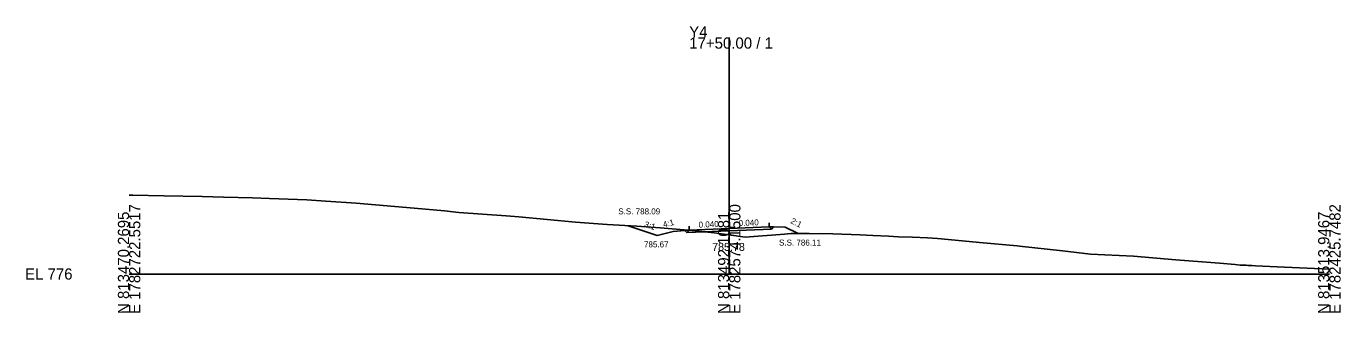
# Model space of a CAD drawing. Extents: x -26 to 3903, y -10 to 9562.
# Drawn here: x -25.7 to 302.8, y 9490.3 to 9562 of the extents above; entities that cross this region are included whole.
import ezdxf

# ---------------------------------------------------------------- set-up
doc = ezdxf.new("R2010")
doc.units = 0
for name, color, linetype in [('Exist Cross Section Cell', 7, 'Continuous'), ('Exist XS Center Line Elevation Label', 7, 'Continuous'), ('Exist XS Ground Line', 7, 'Continuous'), ('Prop XS Ditch Slope Text', 7, 'Continuous'), ('Prop XS Ditch Standard Text', 7, 'Continuous'), ('Prop XS Dump Level', 7, 'Continuous'), ('Prop XS Earthwork Shape', 7, 'Continuous'), ('Prop XS EOT Tick Mark', 7, 'Continuous'), ('Prop XS Finish Grade', 7, 'Continuous'), ('Prop XS Finish Grade Earthwork', 7, 'Continuous'), ('Prop XS Finish Grade Pavement', 7, 'Continuous'), ('Prop XS Pvmt Edge Slope', 7, 'Continuous'), ('Prop XS SE Text', 7, 'Continuous'), ('Prop XS Side Slope Text', 7, 'Continuous'), ('Prop XS SS Elevation Text', 7, 'Continuous'), ('Prop XS Subgrade Earthwork', 7, 'Continuous')]:
    doc.layers.add(name, color=color, linetype=linetype)

msp = doc.modelspace()

# ---------------------------------------------------------------- linework, layer by layer
at = {"layer": 'Exist Cross Section Cell'}
for p, q in [((150, 9500), (150, 9559.19)), ((0, 9500), (150, 9500)), ((150, 9500), (300, 9500))]:
    msp.add_line(p, q, dxfattribs=at)
at = {"layer": 'Exist XS Ground Line'}
for p, q in [((0, 9519.73), (0.95, 9519.72)), ((0.95, 9519.72), (8.66, 9519.54)), ((8.66, 9519.54), (18.3, 9519.42)), ((18.3, 9519.42), (23.59, 9519.22)), ((23.59, 9519.22), (30.83, 9519.04)), ((30.83, 9519.04), (35.09, 9518.88)), ((35.09, 9518.88), (44.46, 9518.54)), ((44.46, 9518.54), (49.19, 9518.2)), ((49.19, 9518.2), (56.76, 9517.76)), ((56.76, 9517.76), (71.27, 9516.51)), ((71.27, 9516.51), (78.85, 9515.81)), ((78.85, 9515.81), (82.41, 9515.41)), ((82.41, 9515.41), (94.26, 9514.55)), ((94.26, 9514.55), (95.37, 9514.47)), ((95.37, 9514.47), (97.41, 9514.31)), ((97.41, 9514.31), (111.58, 9513.01)), ((111.58, 9513.01), (119.53, 9512.39)), ((119.53, 9512.39), (126.88, 9511.97)), ((126.88, 9511.97), (132.73, 9511.53)), ((132.73, 9511.53), (134.72, 9511.38)), ((134.72, 9511.38), (141.73, 9510.78)), ((141.73, 9510.78), (143.87, 9510.55)), ((143.87, 9510.55), (146.24, 9510.3)), ((146.24, 9510.3), (150, 9509.78)), ((150, 9509.78), (153.95, 9509.22)), ((153.95, 9509.22), (163.79, 9509.99)), ((163.79, 9509.99), (165.52, 9510.11)), ((165.52, 9510.11), (169.95, 9510.1)), ((169.95, 9510.1), (175.94, 9510.03)), ((175.94, 9510.03), (182.72, 9509.78)), ((182.72, 9509.78), (185.89, 9509.65)), ((185.89, 9509.65), (189.83, 9509.48)), ((189.83, 9509.48), (192.29, 9509.33)), ((192.29, 9509.33), (195.78, 9509.18)), ((195.78, 9509.18), (199.57, 9509.09)), ((199.57, 9509.09), (202.04, 9508.88)), ((202.04, 9508.88), (208.19, 9508.31)), ((208.19, 9508.31), (212.54, 9507.88)), ((212.54, 9507.88), (221.98, 9507.04)), ((221.98, 9507.04), (222.53, 9506.98)), ((222.53, 9506.98), (233.29, 9505.77)), ((233.29, 9505.77), (240.29, 9504.98)), ((240.29, 9504.98), (251.04, 9504.5)), ((251.04, 9504.5), (261.65, 9503.58)), ((261.65, 9503.58), (272.55, 9502.68)), ((272.55, 9502.68), (276.46, 9502.34)), ((276.46, 9502.34), (277.69, 9502.23)), ((277.69, 9502.23), (279.2, 9502.17)), ((279.2, 9502.17), (279.64, 9502.15)), ((279.64, 9502.15), (280.63, 9502.11)), ((280.63, 9502.11), (281.51, 9502.08)), ((281.51, 9502.08), (286.99, 9501.78)), ((286.99, 9501.78), (300, 9501.25))]:
    msp.add_line(p, q, dxfattribs=at)
at = {"layer": 'Prop XS Dump Level'}
for p, q in [((140, 9510.99), (150, 9511.39)), ((150, 9511.39), (160, 9511.79))]:
    msp.add_line(p, q, dxfattribs=at)
at = {"layer": 'Prop XS Earthwork Shape'}
for points in [[(136, 9510.67), (132, 9509.67), (124.73, 9512.09), (126.88, 9511.97), (132.73, 9511.53), (134.72, 9511.38), (141.73, 9510.78), (143.79, 9510.56), (139.39, 9510.38), (138.87, 9510.9)], [(143.87, 9510.55), (146.24, 9510.3), (150, 9509.78), (153.95, 9509.22), (163.79, 9509.99), (165.52, 9510.11), (167.2, 9510.11), (164, 9511.71), (161.1, 9511.77), (160.56, 9511.23), (150.02, 9510.81), (143.79, 9510.56)]]:
    msp.add_lwpolyline(points, close=True, dxfattribs=at)
at = {"layer": 'Prop XS EOT Tick Mark'}
for p, q in [((140, 9510.99), (140, 9511.99)), ((160, 9511.79), (160, 9512.79))]:
    msp.add_line(p, q, dxfattribs=at)
at = {"layer": 'Prop XS Finish Grade'}
for p, q in [((160, 9511.79), (161.1, 9511.77)), ((140, 9510.99), (138.87, 9510.9))]:
    msp.add_line(p, q, dxfattribs=at)
at = {"layer": 'Prop XS Finish Grade Earthwork'}
for p, q in [((132, 9509.67), (124.73, 9512.09)), ((161.1, 9511.77), (164, 9511.71)), ((164, 9511.71), (167.2, 9510.11)), ((136, 9510.67), (132, 9509.67)), ((138.87, 9510.9), (136, 9510.67))]:
    msp.add_line(p, q, dxfattribs=at)
at = {"layer": 'Prop XS Finish Grade Pavement'}
for p, q in [((140, 9510.99), (150, 9511.39)), ((150, 9511.39), (160, 9511.79))]:
    msp.add_line(p, q, dxfattribs=at)
at = {"layer": 'Prop XS Pvmt Edge Slope'}
for p, q in [((160, 9511.79), (160.56, 9511.23)), ((140, 9510.99), (139.39, 9510.38))]:
    msp.add_line(p, q, dxfattribs=at)
at = {"layer": 'Prop XS Subgrade Earthwork'}
for p, q in [((150.02, 9510.81), (160.56, 9511.23)), ((160.56, 9511.23), (161.1, 9511.77)), ((139.39, 9510.38), (138.87, 9510.9)), ((139.39, 9510.38), (150.02, 9510.81))]:
    msp.add_line(p, q, dxfattribs=at)

# ---------------------------------------------------------------- texts
at = {"layer": 'Exist Cross Section Cell'}
for s, p in [('Y4', (140, 9559.19)), ('17+50.00 / 1', (140, 9556.39)), ('EL 776', (-26, 9498.6))]:
    msp.add_text(s, height=2.8, dxfattribs=at).set_placement(p)
for s, p in [('N 813470.2695', (0, 9490)), ('E 1782722.5517', (2.8, 9490)), ('N 813492.1081', (150, 9490)), ('E 1782574.1500', (152.8, 9490)), ('N 813513.9467', (300, 9490)), ('E 1782425.7482', (302.8, 9490))]:
    msp.add_text(s, height=2.8, rotation=90, dxfattribs=at).set_placement(p)
at = {"layer": 'Exist XS Center Line Elevation Label'}
msp.add_text('785.78', height=2, dxfattribs=at).set_placement((145.73, 9505.78))
at = {"layer": 'Prop XS Ditch Slope Text'}
msp.add_text('4:1', height=1.5, rotation=14.0362, dxfattribs=at).set_placement((133.64, 9511.62))
at = {"layer": 'Prop XS Ditch Standard Text'}
msp.add_text('785.67', height=1.5, dxfattribs=at).set_placement((128.7, 9506.67))
at = {"layer": 'Prop XS Dump Level'}
for p in [(164, 9511.67), (136, 9510.63)]:
    msp.add_text('Case1', height=0.04, dxfattribs=at).set_placement(p)
at = {"layer": 'Prop XS SE Text'}
for p in [(142.38, 9511.58), (152.38, 9511.98)]:
    msp.add_text('0.040', height=1.5, rotation=2.2906, dxfattribs=at).set_placement(p)
at = {"layer": 'Prop XS Side Slope Text'}
for s, rotation, p in [('3:1', 342.2871, (128.63, 9511.83)), ('2:1', 333.4349, (165.19, 9512.79))]:
    msp.add_text(s, height=1.5, rotation=rotation, dxfattribs=at).set_placement(p)
at = {"layer": 'Prop XS SS Elevation Text'}
for s, p in [('S.S. 788.09', (122.27, 9514.92)), ('S.S. 786.11', (162.45, 9507.11))]:
    msp.add_text(s, height=1.5, dxfattribs=at).set_placement(p)

doc.saveas('drawing.dxf')
